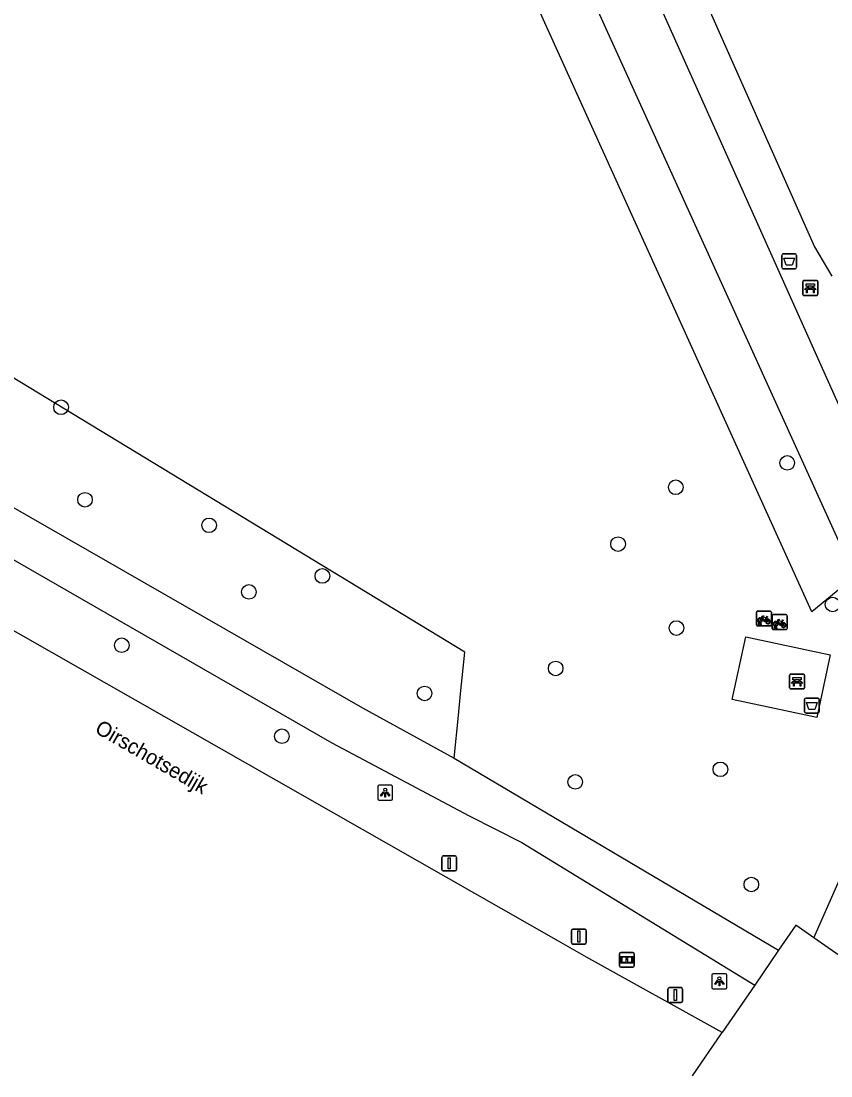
# Model space of a CAD drawing. Extents: x 157154 to 159278, y 385000 to 386650.
# Drawn here: x 159015.6 to 159069.8, y 384999.6 to 385070.3 of the extents above; entities that cross this region are included whole.
import ezdxf

# ---------------------------------------------------------------- set-up
doc = ezdxf.new("R2010")
doc.units = 0
for name, color, linetype in [('IMGEO_Afvalbak', 7, 'Continuous'), ('IMGEO_Bank', 7, 'Continuous'), ('IMGEO_Boom', 7, 'Continuous'), ('IMGEO_Fietsenrek', 7, 'Continuous'), ('IMGEO_Gemengd_bos', 7, 'Continuous'), ('IMGEO_Groenvoorziening', 7, 'Continuous'), ('IMGEO_Informatiebord', 7, 'Continuous'), ('IMGEO_Lichtpunt', 7, 'Continuous'), ('IMGEO_Openbare_ruimte_label', 7, 'Continuous'), ('IMGEO_Rijbaan_lokaal_gesloten', 7, 'Continuous'), ('IMGEO_Verkeersbordpaal', 7, 'Continuous'), ('IMGEO_Voetpad_halfverhard', 7, 'Continuous'), ('IMGEO_Voetpad_open', 7, 'Continuous')]:
    doc.layers.add(name, color=color, linetype=linetype)

msp = doc.modelspace()

# ---------------------------------------------------------------- linework, layer by layer
at = {"layer": 'IMGEO_Afvalbak'}
for p, q in [((159066.505, 385053.77), (159066.505, 385054.57)), ((159066.505, 385054.57), (159066.505, 385053.77)), ((159066.605, 385054.67), (159067.395, 385054.67)), ((159067.395, 385054.67), (159066.605, 385054.67)), ((159067.495, 385054.57), (159067.495, 385053.77)), ((159067.495, 385053.77), (159067.495, 385054.57)), ((159067.395, 385053.67), (159066.605, 385053.67)), ((159066.605, 385053.67), (159067.395, 385053.67)), ((159068.026, 385024.035), (159068.026, 385024.835)), ((159068.026, 385024.835), (159068.026, 385024.035)), ((159068.126, 385024.935), (159068.916, 385024.935)), ((159068.916, 385024.935), (159068.126, 385024.935)), ((159069.016, 385024.835), (159069.016, 385024.035)), ((159069.016, 385024.035), (159069.016, 385024.835)), ((159068.916, 385023.935), (159068.126, 385023.935)), ((159068.126, 385023.935), (159068.916, 385023.935))]:
    msp.add_line(p, q, dxfattribs=at)
for points in [[(159066.648, 385054.384), (159067.352, 385054.384), (159067.203, 385053.914), (159066.797, 385053.914), (159066.648, 385054.384)], [(159068.169, 385024.649), (159068.873, 385024.649), (159068.724, 385024.179), (159068.318, 385024.179), (159068.169, 385024.649)]]:
    msp.add_lwpolyline(points, dxfattribs=at)
for centre, start, end in [((159066.605, 385054.57), 90, 180), ((159066.605, 385054.57), 90, 180), ((159067.395, 385054.57), 0, 90), ((159067.395, 385054.57), 360, 90), ((159066.605, 385053.77), 180, 270), ((159066.605, 385053.77), 180, 270), ((159067.395, 385053.77), 270, 0), ((159067.395, 385053.77), 270, 0), ((159068.126, 385024.835), 90, 180), ((159068.126, 385024.835), 90, 180), ((159068.916, 385024.835), 0, 90), ((159068.916, 385024.835), 360, 90), ((159068.126, 385024.035), 180, 270), ((159068.126, 385024.035), 180, 270), ((159068.916, 385024.035), 270, 0), ((159068.916, 385024.035), 270, 0)]:
    msp.add_arc(centre, 0.1, start, end, dxfattribs=at)
at = {"layer": 'IMGEO_Bank'}
for p, q in [((159067.915, 385051.96), (159067.915, 385052.801)), ((159067.915, 385052.801), (159067.915, 385051.96)), ((159067.99, 385052.885), (159068.831, 385052.885)), ((159068.831, 385052.885), (159067.99, 385052.885)), ((159068.915, 385052.81), (159068.915, 385051.969)), ((159068.915, 385051.969), (159068.915, 385052.81)), ((159068.612, 385052.283), (159068.219, 385052.283)), ((159068.224, 385052.391), (159068.224, 385052.497)), ((159068.268, 385052.497), (159068.268, 385052.391)), ((159068.556, 385052.503), (159068.274, 385052.503)), ((159068.274, 385052.385), (159068.556, 385052.385)), ((159068.562, 385052.391), (159068.562, 385052.497)), ((159068.606, 385052.497), (159068.606, 385052.391)), ((159068.84, 385051.885), (159067.999, 385051.885)), ((159067.999, 385051.885), (159068.84, 385051.885)), ((159067.104, 385026.543), (159067.945, 385026.543)), ((159067.945, 385026.543), (159067.104, 385026.543)), ((159067.029, 385025.618), (159067.029, 385026.459)), ((159067.029, 385026.459), (159067.029, 385025.618)), ((159067.726, 385025.941), (159067.333, 385025.941)), ((159067.338, 385026.049), (159067.338, 385026.155)), ((159067.382, 385026.155), (159067.382, 385026.049)), ((159067.67, 385026.161), (159067.388, 385026.161)), ((159067.388, 385026.043), (159067.67, 385026.043)), ((159067.676, 385026.049), (159067.676, 385026.155)), ((159067.72, 385026.155), (159067.72, 385026.049)), ((159068.029, 385026.468), (159068.029, 385025.627)), ((159068.029, 385025.627), (159068.029, 385026.468)), ((159067.954, 385025.543), (159067.113, 385025.543)), ((159067.113, 385025.543), (159067.954, 385025.543))]:
    msp.add_line(p, q, dxfattribs=at)
for points in [[(159068.218, 385052.503), (159068.132, 385052.503), (159068.132, 385052.664), (159068.695, 385052.664), (159068.695, 385052.503), (159068.612, 385052.503)], [(159068.162, 385052.283), (159068.02, 385052.283), (159068.132, 385052.385), (159068.218, 385052.385)], [(159068.212, 385052.276), (159068.212, 385052.069), (159068.169, 385052.069), (159068.169, 385052.276)], [(159068.612, 385052.385), (159068.695, 385052.385), (159068.807, 385052.283), (159068.668, 385052.283)], [(159068.662, 385052.276), (159068.662, 385052.069), (159068.618, 385052.069), (159068.618, 385052.276)], [(159067.276, 385025.941), (159067.134, 385025.941), (159067.246, 385026.043), (159067.332, 385026.043)], [(159067.332, 385026.161), (159067.246, 385026.161), (159067.246, 385026.322), (159067.809, 385026.322), (159067.809, 385026.161), (159067.726, 385026.161)], [(159067.326, 385025.934), (159067.326, 385025.727), (159067.283, 385025.727), (159067.283, 385025.934)], [(159067.726, 385026.043), (159067.809, 385026.043), (159067.921, 385025.941), (159067.782, 385025.941)], [(159067.776, 385025.934), (159067.776, 385025.727), (159067.732, 385025.727), (159067.732, 385025.934)]]:
    msp.add_lwpolyline(points, dxfattribs=at)
for centre, radius, start, end in [((159067.993, 385052.807), 0.0779, 92.4484, 184.28452), ((159067.993, 385052.807), 0.0779, 92.4484, 184.28452), ((159068.837, 385052.807), 0.0779, 2.4484, 94.28452), ((159068.837, 385052.807), 0.0779, 2.4484, 94.28452), ((159067.993, 385051.963), 0.0779, 182.4484, 274.28452), ((159067.993, 385051.963), 0.0779, 182.4484, 274.28452), ((159068.162, 385052.276), 0.00671, 2.89567, 87.10433), ((159068.219, 385052.276), 0.00671, 92.89567, 177.10433), ((159068.217, 385052.496), 0.00671, 2.89567, 87.10433), ((159068.217, 385052.392), 0.00671, 272.89567, 357.10433), ((159068.274, 385052.496), 0.00671, 92.89567, 177.10433), ((159068.274, 385052.392), 0.00671, 182.89567, 267.10433), ((159068.556, 385052.496), 0.00671, 2.89567, 87.10433), ((159068.556, 385052.392), 0.00671, 272.89567, 357.10433), ((159068.613, 385052.496), 0.00671, 92.89567, 177.10433), ((159068.613, 385052.392), 0.00671, 182.89567, 267.10433), ((159068.611, 385052.276), 0.00671, 2.89567, 87.10433), ((159068.668, 385052.276), 0.00671, 92.89567, 177.10433), ((159068.837, 385051.963), 0.0779, 272.4484, 4.28452), ((159068.837, 385051.963), 0.0779, 272.4484, 4.28452), ((159067.107, 385026.465), 0.0779, 92.4484, 184.28452), ((159067.107, 385026.465), 0.0779, 92.4484, 184.28452), ((159067.951, 385026.465), 0.0779, 2.4484, 94.28452), ((159067.951, 385026.465), 0.0779, 2.4484, 94.28452), ((159067.276, 385025.934), 0.00671, 2.89567, 87.10433), ((159067.333, 385025.934), 0.00671, 92.89567, 177.10433), ((159067.331, 385026.154), 0.00671, 2.89567, 87.10433), ((159067.331, 385026.05), 0.00671, 272.89567, 357.10433), ((159067.388, 385026.154), 0.00671, 92.89567, 177.10433), ((159067.388, 385026.05), 0.00671, 182.89567, 267.10433), ((159067.67, 385026.154), 0.00671, 2.89567, 87.10433), ((159067.67, 385026.05), 0.00671, 272.89567, 357.10433), ((159067.727, 385026.154), 0.00671, 92.89567, 177.10433), ((159067.727, 385026.05), 0.00671, 182.89567, 267.10433), ((159067.725, 385025.934), 0.00671, 2.89567, 87.10433), ((159067.782, 385025.934), 0.00671, 92.89567, 177.10433), ((159067.107, 385025.621), 0.0779, 182.4484, 274.28452), ((159067.107, 385025.621), 0.0779, 182.4484, 274.28452), ((159067.951, 385025.621), 0.0779, 272.4484, 4.28452), ((159067.951, 385025.621), 0.0779, 272.4484, 4.28452)]:
    msp.add_arc(centre, radius, start, end, dxfattribs=at)
at = {"layer": 'IMGEO_Boom'}
for centre in [(159018.252, 385044.398), (159066.867, 385040.68), (159059.41, 385039.043), (159019.855, 385038.21), (159028.166, 385036.499), (159055.543, 385035.24), (159035.748, 385033.109), (159030.828, 385032.043), (159069.907, 385031.198), (159059.454, 385029.622), (159022.319, 385028.47), (159051.367, 385026.915), (159042.59, 385025.245), (159033.037, 385022.378), (159062.393, 385020.164), (159052.678, 385019.326), (159064.466, 385012.455)]:
    msp.add_circle(centre, 0.489, dxfattribs=at)
at = {"layer": 'IMGEO_Fietsenrek'}
for p, q in [((159064.883, 385030.76), (159065.724, 385030.76)), ((159065.724, 385030.76), (159064.883, 385030.76)), ((159064.808, 385029.835), (159064.808, 385030.676)), ((159064.808, 385030.676), (159064.808, 385029.835)), ((159065.046, 385030.016), (159065.045, 385030.02)), ((159065.077, 385030.027), (159065.078, 385030.02)), ((159065.495, 385030.309), (159065.531, 385030.214)), ((159065.808, 385030.685), (159065.808, 385029.844)), ((159065.808, 385029.844), (159065.808, 385030.685)), ((159065.858, 385029.593), (159065.858, 385030.434)), ((159065.858, 385030.434), (159065.858, 385029.593)), ((159065.933, 385030.518), (159066.774, 385030.518)), ((159066.774, 385030.518), (159065.933, 385030.518)), ((159066.545, 385030.067), (159066.581, 385029.972)), ((159066.858, 385030.443), (159066.858, 385029.602)), ((159066.858, 385029.602), (159066.858, 385030.443)), ((159065.733, 385029.76), (159064.892, 385029.76)), ((159064.892, 385029.76), (159065.733, 385029.76)), ((159064.935, 385029.844), (159064.974, 385030.004)), ((159064.969, 385029.844), (159064.935, 385029.844)), ((159065.004, 385029.992), (159064.969, 385029.844)), ((159065.087, 385029.844), (159065.053, 385029.986)), ((159065.085, 385029.99), (159065.12, 385029.844)), ((159065.12, 385029.844), (159065.087, 385029.844)), ((159066.783, 385029.518), (159065.942, 385029.518)), ((159065.942, 385029.518), (159066.783, 385029.518)), ((159065.985, 385029.602), (159066.024, 385029.762)), ((159066.019, 385029.602), (159065.985, 385029.602)), ((159066.054, 385029.75), (159066.019, 385029.602)), ((159066.096, 385029.774), (159066.095, 385029.778)), ((159066.137, 385029.602), (159066.103, 385029.744)), ((159066.127, 385029.785), (159066.128, 385029.778)), ((159066.135, 385029.748), (159066.17, 385029.602)), ((159066.17, 385029.602), (159066.137, 385029.602))]:
    msp.add_line(p, q, dxfattribs=at)
for points in [[(159065.142, 385030.234), (159065.09, 385030.144), (159065.05, 385030.119), (159065.051, 385030.166), (159065.106, 385030.26)], [(159065.121, 385030.286), (159065.216, 385030.45), (159065.302, 385030.436), (159065.304, 385030.427), (159065.248, 385030.416), (159065.221, 385030.371), (159065.477, 385030.33)], [(159065.417, 385030.042), (159065.367, 385030.042), (159065.176, 385030.293), (159065.157, 385030.261)], [(159065.464, 385030.305), (159065.207, 385030.346), (159065.19, 385030.317), (159065.357, 385030.097), (159065.464, 385030.305)], [(159065.512, 385030.207), (159065.482, 385030.284), (159065.373, 385030.066), (159065.416, 385030.066)], [(159065.446, 385030.066), (159065.566, 385030.065), (159065.522, 385030.179)], [(159065.542, 385030.186), (159065.597, 385030.041), (159065.447, 385030.041)], [(159065.477, 385030.33), (159065.502, 385030.379), (159065.496, 385030.383), (159065.473, 385030.387), (159065.461, 385030.394), (159065.46, 385030.397), (159065.462, 385030.402), (159065.557, 385030.387), (159065.559, 385030.377), (159065.549, 385030.364), (159065.537, 385030.358), (159065.523, 385030.364), (159065.495, 385030.309)], [(159066.192, 385029.992), (159066.14, 385029.902), (159066.1, 385029.877), (159066.101, 385029.924), (159066.156, 385030.018)], [(159066.171, 385030.044), (159066.266, 385030.208), (159066.352, 385030.194), (159066.354, 385030.185), (159066.298, 385030.174), (159066.271, 385030.129), (159066.527, 385030.088)], [(159066.467, 385029.8), (159066.417, 385029.8), (159066.226, 385030.051), (159066.207, 385030.019)], [(159066.514, 385030.063), (159066.257, 385030.104), (159066.24, 385030.075), (159066.407, 385029.855), (159066.514, 385030.063)], [(159066.562, 385029.965), (159066.532, 385030.042), (159066.423, 385029.824), (159066.466, 385029.824)], [(159066.527, 385030.088), (159066.552, 385030.137), (159066.546, 385030.141), (159066.523, 385030.145), (159066.511, 385030.152), (159066.51, 385030.155), (159066.512, 385030.16), (159066.607, 385030.145), (159066.609, 385030.135), (159066.599, 385030.122), (159066.587, 385030.116), (159066.573, 385030.122), (159066.545, 385030.067)], [(159066.496, 385029.824), (159066.616, 385029.823), (159066.572, 385029.937)], [(159066.592, 385029.944), (159066.647, 385029.799), (159066.497, 385029.799)]]:
    msp.add_lwpolyline(points, dxfattribs=at)
for centre, radius, start, end in [((159064.886, 385030.682), 0.0779, 92.4484, 184.28452), ((159064.886, 385030.682), 0.0779, 92.4484, 184.28452), ((159065.73, 385030.682), 0.0779, 2.4484, 94.28452), ((159065.73, 385030.682), 0.0779, 2.4484, 94.28452), ((159065.048, 385030.145), 0.159, 62.67661, 242.13685), ((159065.048, 385030.145), 0.129, 63.31916, 238.90302), ((159065.028, 385030.016), 0.0499, 12.8025, 158.69338), ((159065.028, 385030.016), 0.0174, 12.8025, 163.45023), ((159065.048, 385030.145), 0.129, 253.41502, 269.02044), ((159065.048, 385030.145), 0.129, 283.60429, 43.43025), ((159065.048, 385030.145), 0.159, 283.5766, 46.60424), ((159065.575, 385030.061), 0.159, 113.3408, 178.32165), ((159065.575, 385030.061), 0.159, 187.0065, 105.77075), ((159065.575, 385030.061), 0.129, 113.92302, 177.95563), ((159065.575, 385030.061), 0.129, 188.67146, 104.58832), ((159065.936, 385030.44), 0.0779, 92.4484, 184.28452), ((159065.936, 385030.44), 0.0779, 92.4484, 184.28452), ((159066.098, 385029.903), 0.159, 62.67661, 242.13685), ((159066.098, 385029.903), 0.129, 63.31916, 238.90302), ((159066.098, 385029.903), 0.159, 283.5766, 46.60424), ((159066.78, 385030.44), 0.0779, 2.4484, 94.28452), ((159066.78, 385030.44), 0.0779, 2.4484, 94.28452), ((159064.886, 385029.838), 0.0779, 182.4484, 274.28452), ((159064.886, 385029.838), 0.0779, 182.4484, 274.28452), ((159065.048, 385030.145), 0.159, 253.99666, 271.78671), ((159065.73, 385029.838), 0.0779, 272.4484, 4.28452), ((159065.73, 385029.838), 0.0779, 272.4484, 4.28452), ((159065.936, 385029.596), 0.0779, 182.4484, 274.28452), ((159065.936, 385029.596), 0.0779, 182.4484, 274.28452), ((159066.078, 385029.774), 0.0499, 12.8025, 158.69338), ((159066.098, 385029.903), 0.159, 253.99666, 271.78671), ((159066.078, 385029.774), 0.0174, 12.8025, 163.45023), ((159066.098, 385029.903), 0.129, 253.41502, 269.02044), ((159066.098, 385029.903), 0.129, 283.60429, 43.43025), ((159066.625, 385029.819), 0.159, 113.3408, 178.32165), ((159066.625, 385029.819), 0.159, 187.0065, 105.77075), ((159066.625, 385029.819), 0.129, 113.92302, 177.95563), ((159066.625, 385029.819), 0.129, 188.67146, 104.58832), ((159066.78, 385029.596), 0.0779, 272.4484, 4.28452), ((159066.78, 385029.596), 0.0779, 272.4484, 4.28452)]:
    msp.add_arc(centre, radius, start, end, dxfattribs=at)
at = {"layer": 'IMGEO_Gemengd_bos'}
for points in [[(159044.566, 385020.904), (159044.854, 385023.771), (159044.999, 385025.216), (159045.279, 385028.002), (159000, 385055.503), (158983.569, 385065.693), (158991.494, 385068.31), (158999.672, 385074.26), (159003.066, 385078.986), (159005.681, 385085.492), (159006.793, 385090.941), (159011.021, 385097.836), (159014.526, 385101.394), (159019.885, 385109.998), (159022.5, 385115.67), (159021.735, 385127.229), (159021.108, 385130.984), (159018.615, 385137.396), (159014.574, 385143.725), (159010.236, 385148.223)], [(159050.473, 385096.209), (159068.689, 385055.139), (159069.845, 385053.174)]]:
    msp.add_lwpolyline(points, dxfattribs=at)
at = {"layer": 'IMGEO_Groenvoorziening'}
for points in [[(159071.37, 385033.085), (159071.143, 385032.868), (159068.515, 385030.696), (159027.263, 385121.739), (159013.145, 385153.422)], [(159069.741, 385027.825), (159068.843, 385023.634), (159063.193, 385024.846), (159064.091, 385029.036), (159069.741, 385027.825)], [(159068.646, 385008.884), (159067.434, 385009.722), (159066.288, 385008.051)], [(159064.692, 385005.722), (159062.513, 385002.544)]]:
    msp.add_lwpolyline(points, dxfattribs=at)
at = {"layer": 'IMGEO_Informatiebord'}
for p, q in [((159055.635, 385007.014), (159055.635, 385007.814)), ((159055.635, 385007.814), (159055.635, 385007.014)), ((159055.735, 385007.914), (159056.525, 385007.914)), ((159056.525, 385007.914), (159055.735, 385007.914)), ((159056.625, 385007.814), (159056.625, 385007.014)), ((159056.625, 385007.014), (159056.625, 385007.814)), ((159056.525, 385006.914), (159055.735, 385006.914)), ((159055.735, 385006.914), (159056.525, 385006.914))]:
    msp.add_line(p, q, dxfattribs=at)
for points in [[(159055.736, 385007.646), (159056.524, 385007.646), (159056.524, 385007.182), (159055.736, 385007.182), (159055.736, 385007.646)], [(159055.801, 385007.581), (159055.801, 385007.247), (159056.076, 385007.247), (159056.077, 385007.46), (159056.181, 385007.461), (159056.182, 385007.247), (159056.459, 385007.247), (159056.459, 385007.581), (159056.183, 385007.581), (159056.183, 385007.501), (159056.077, 385007.501), (159056.077, 385007.581), (159055.801, 385007.581)]]:
    msp.add_lwpolyline(points, dxfattribs=at)
for centre, start, end in [((159055.735, 385007.814), 90, 180), ((159055.735, 385007.814), 90, 180), ((159056.525, 385007.814), 0, 90), ((159056.525, 385007.814), 360, 90), ((159055.735, 385007.014), 180, 270), ((159055.735, 385007.014), 180, 270), ((159056.525, 385007.014), 270, 0), ((159056.525, 385007.014), 270, 0)]:
    msp.add_arc(centre, 0.1, start, end, dxfattribs=at)
at = {"layer": 'IMGEO_Lichtpunt'}
for p, q in [((159039.455, 385019.002), (159039.455, 385018.195)), ((159039.455, 385019.002), (159039.455, 385018.195)), ((159040.357, 385019.097), (159039.549, 385019.097)), ((159040.357, 385019.097), (159039.549, 385019.097)), ((159040.451, 385018.195), (159040.451, 385019.002)), ((159040.451, 385018.195), (159040.451, 385019.002)), ((159039.549, 385018.101), (159040.357, 385018.101)), ((159039.549, 385018.101), (159040.357, 385018.101)), ((159061.827, 385006.378), (159061.827, 385005.571)), ((159061.827, 385006.378), (159061.827, 385005.571)), ((159062.729, 385006.473), (159061.921, 385006.473)), ((159062.729, 385006.473), (159061.921, 385006.473)), ((159062.823, 385005.571), (159062.823, 385006.378)), ((159062.823, 385005.571), (159062.823, 385006.378)), ((159061.921, 385005.477), (159062.729, 385005.477)), ((159061.921, 385005.477), (159062.729, 385005.477))]:
    msp.add_line(p, q, dxfattribs=at)
for points in [[(159039.829, 385018.666), (159039.868, 385018.638), (159039.68, 385018.376), (159039.642, 385018.403), (159039.829, 385018.666)], [(159039.931, 385018.618), (159039.978, 385018.618), (159039.978, 385018.296), (159039.931, 385018.296), (159039.931, 385018.618)], [(159040.041, 385018.638), (159040.079, 385018.665), (159040.266, 385018.403), (159040.227, 385018.375), (159040.041, 385018.638)], [(159062.201, 385006.042), (159062.24, 385006.014), (159062.052, 385005.752), (159062.014, 385005.779), (159062.201, 385006.042)], [(159062.413, 385006.014), (159062.451, 385006.041), (159062.638, 385005.779), (159062.599, 385005.751), (159062.413, 385006.014)], [(159062.303, 385005.994), (159062.35, 385005.994), (159062.35, 385005.672), (159062.303, 385005.672), (159062.303, 385005.994)]]:
    msp.add_lwpolyline(points, dxfattribs=at)
for centre in [(159039.954, 385018.8), (159062.326, 385006.176)]:
    msp.add_circle(centre, 0.0994, dxfattribs=at)
for centre, start, end in [((159039.549, 385019.002), 90, 180), ((159039.549, 385019.002), 90, 180), ((159040.357, 385019.002), 0, 90), ((159040.357, 385019.002), 0, 90), ((159039.549, 385018.195), 180, 270), ((159039.549, 385018.195), 180, 270), ((159040.357, 385018.195), 270, 0), ((159040.357, 385018.195), 270, 360), ((159061.921, 385006.378), 90, 180), ((159061.921, 385006.378), 90, 180), ((159062.729, 385006.378), 0, 90), ((159062.729, 385006.378), 0, 90), ((159061.921, 385005.571), 180, 270), ((159061.921, 385005.571), 180, 270), ((159062.729, 385005.571), 270, 0), ((159062.729, 385005.571), 270, 360)]:
    msp.add_arc(centre, 0.0946, start, end, dxfattribs=at)
at = {"layer": 'IMGEO_Rijbaan_lokaal_gesloten'}
for points in [[(159062.513, 385002.544), (159053.436, 385007.595), (159051.559, 385008.655), (158991.219, 385043.034), (158951.346, 385065.855)], [(159060.524, 384999.643), (159062.513, 385002.544)]]:
    msp.add_lwpolyline(points, dxfattribs=at)
at = {"layer": 'IMGEO_Verkeersbordpaal'}
for p, q in [((159043.743, 385013.47), (159043.743, 385014.27)), ((159043.743, 385014.27), (159043.743, 385013.47)), ((159043.843, 385014.37), (159044.633, 385014.37)), ((159044.633, 385014.37), (159043.843, 385014.37)), ((159044.733, 385014.27), (159044.733, 385013.47)), ((159044.733, 385013.47), (159044.733, 385014.27)), ((159044.633, 385013.37), (159043.843, 385013.37)), ((159043.843, 385013.37), (159044.633, 385013.37)), ((159052.424, 385008.568), (159052.424, 385009.368)), ((159052.424, 385009.368), (159052.424, 385008.568)), ((159052.524, 385009.468), (159053.314, 385009.468)), ((159053.314, 385009.468), (159052.524, 385009.468)), ((159053.414, 385009.368), (159053.414, 385008.568)), ((159053.414, 385008.568), (159053.414, 385009.368)), ((159053.314, 385008.468), (159052.524, 385008.468)), ((159052.524, 385008.468), (159053.314, 385008.468)), ((159058.877, 385004.656), (159058.877, 385005.456)), ((159058.877, 385005.456), (159058.877, 385004.656)), ((159058.977, 385005.556), (159059.767, 385005.556)), ((159059.767, 385005.556), (159058.977, 385005.556)), ((159059.867, 385005.456), (159059.867, 385004.656)), ((159059.867, 385004.656), (159059.867, 385005.456)), ((159059.767, 385004.556), (159058.977, 385004.556)), ((159058.977, 385004.556), (159059.767, 385004.556))]:
    msp.add_line(p, q, dxfattribs=at)
for points in [[(159044.163, 385014.245), (159044.313, 385014.245), (159044.313, 385013.495), (159044.163, 385013.495), (159044.163, 385014.245)], [(159052.844, 385009.343), (159052.994, 385009.343), (159052.994, 385008.593), (159052.844, 385008.593), (159052.844, 385009.343)], [(159059.297, 385005.431), (159059.447, 385005.431), (159059.447, 385004.681), (159059.297, 385004.681), (159059.297, 385005.431)]]:
    msp.add_lwpolyline(points, dxfattribs=at)
for centre, start, end in [((159043.843, 385014.27), 90, 180), ((159043.843, 385014.27), 90, 180), ((159044.633, 385014.27), 0, 90), ((159044.633, 385014.27), 360, 90), ((159043.843, 385013.47), 180, 270), ((159043.843, 385013.47), 180, 270), ((159044.633, 385013.47), 270, 0), ((159044.633, 385013.47), 270, 0), ((159052.524, 385009.368), 90, 180), ((159052.524, 385009.368), 90, 180), ((159053.314, 385009.368), 0, 90), ((159053.314, 385009.368), 360, 90), ((159052.524, 385008.568), 180, 270), ((159052.524, 385008.568), 180, 270), ((159053.314, 385008.568), 270, 0), ((159053.314, 385008.568), 270, 0), ((159058.977, 385005.456), 90, 180), ((159058.977, 385005.456), 90, 180), ((159059.767, 385005.456), 0, 90), ((159059.767, 385005.456), 360, 90), ((159058.977, 385004.656), 180, 270), ((159058.977, 385004.656), 180, 270), ((159059.767, 385004.656), 270, 0), ((159059.767, 385004.656), 270, 0)]:
    msp.add_arc(centre, 0.1, start, end, dxfattribs=at)
at = {"layer": 'IMGEO_Voetpad_halfverhard'}
for points in [[(159075.621, 385039.356), (159072.867, 385040.902), (159071.266, 385042.455), (159048.344, 385093.622), (159019.724, 385156.991)], [(159015.899, 385155.76), (159044.824, 385091.61), (159071.37, 385033.085)], [(159068.646, 385008.884), (159070.784, 385013.725)], [(159070.867, 385007.347), (159068.646, 385008.884)]]:
    msp.add_lwpolyline(points, dxfattribs=at)
at = {"layer": 'IMGEO_Voetpad_open'}
for points in [[(158953.292, 385069.711), (159036.37, 385021.937), (159045.577, 385017.044), (159049.104, 385015.263), (159064.692, 385005.722)], [(158960.501, 385069.295), (158994.894, 385049.258), (159038.423, 385024.282), (159044.566, 385020.904)], [(159044.566, 385020.904), (159066.288, 385008.051)], [(159066.288, 385008.051), (159064.692, 385005.722)]]:
    msp.add_lwpolyline(points, dxfattribs=at)

# ---------------------------------------------------------------- texts
at = {"layer": 'IMGEO_Openbare_ruimte_label'}
msp.add_text('Oirschotsedijk', height=1, rotation=329.99927, dxfattribs=at).set_placement((159020.449, 385022.66))

doc.saveas('drawing.dxf')
